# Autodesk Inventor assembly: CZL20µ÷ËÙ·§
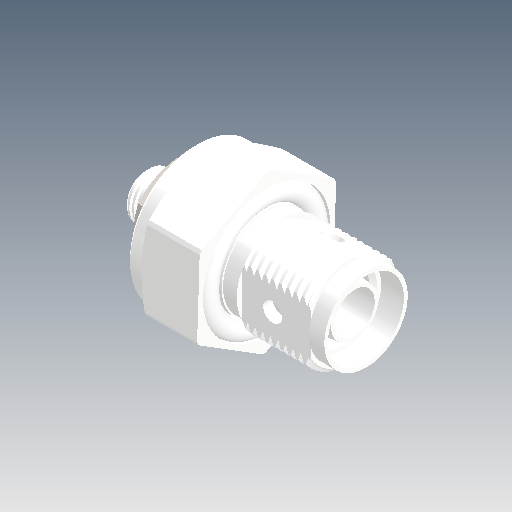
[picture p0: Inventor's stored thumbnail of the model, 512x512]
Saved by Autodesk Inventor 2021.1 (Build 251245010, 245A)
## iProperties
Created: 2021-05
Part Number: CZL20µ÷ËÙ·§
Document SubType Name: Assembly
Designer: user
Author: user
Revision Number: ÈÎºÎ
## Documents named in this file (4)
- D:\Vault_2016\Projekty\Clamptek\Hydraulic\CHLC\CHLC-40\Inventor\CHLC-FAMT40L\CZL20µ÷ËÙ·§.iam
- D:\Vault_2016\Projekty\Clamptek\Hydraulic\CHLC\CHLC-40\Inventor\CHLC-FAMT40L\20·§Ìå.ipt
- D:\Vault_2016\Projekty\Clamptek\Hydraulic\CHLC\CHLC-40\Inventor\CHLC-FAMT40L\20µ÷ËÙ¸Ë.ipt
- D:\Vault_2016\Projekty\Clamptek\Hydraulic\CHLC\CHLC-40\Inventor\CHLC-FAMT40L\hex thin nuts-grades ab-chamfered gb(GB_FASTENER_NUT_STNAB M6-S).ipt
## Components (3 placed, 3 different names)
1. 20·§Ìå_20
2. 20µ÷ËÙ¸Ë_21
3. hex thin nuts-grades ab-chamfered gb(GB_FASTENER_NUT_STNAB M6-S)_22
